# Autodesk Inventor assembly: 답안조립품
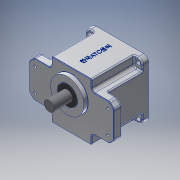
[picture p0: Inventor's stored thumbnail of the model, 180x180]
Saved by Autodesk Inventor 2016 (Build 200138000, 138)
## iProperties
Created: 2017-01
Part Number: 답안조립품
Material: 일반
Document SubType Name: Assembly
Designer: Owner
Author: Owner
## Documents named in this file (10)
- C:\Users\Owner\Desktop\470111V1016\답안조립품.iam
- C:\Users\Owner\Desktop\470111V1016\본체.ipt
- C:\Users\Owner\Desktop\470111V1016\메인축.ipt
- C:\Users\Owner\Desktop\470111V1016\베어링 608.ipt
- C:\Users\Owner\Desktop\470111V1016\베어링 6003.ipt
- C:\Users\Owner\Desktop\470111V1016\볼트 M4 x 10.ipt
- C:\Users\Owner\Desktop\470111V1016\서브축.ipt
- C:\Users\Owner\Desktop\470111V1016\오일실 8 22 7.ipt
- C:\Users\Owner\Desktop\470111V1016\오일실 17 32 8.ipt
- C:\Users\Owner\Desktop\470111V1016\커버.ipt
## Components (2 placed, 1 different names)
1. ISO 4762 M4 x 10:1
2. ISO 4762 M4 x 10:2
